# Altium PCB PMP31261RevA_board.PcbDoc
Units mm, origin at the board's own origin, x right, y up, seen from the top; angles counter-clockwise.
Board outline 58.42 x 41.91 mm, 2 copper layers (Top Layer, Bottom Layer), stack 1.575 mm thick; 35 components, 18 nets, 85 pads, 16 vias.
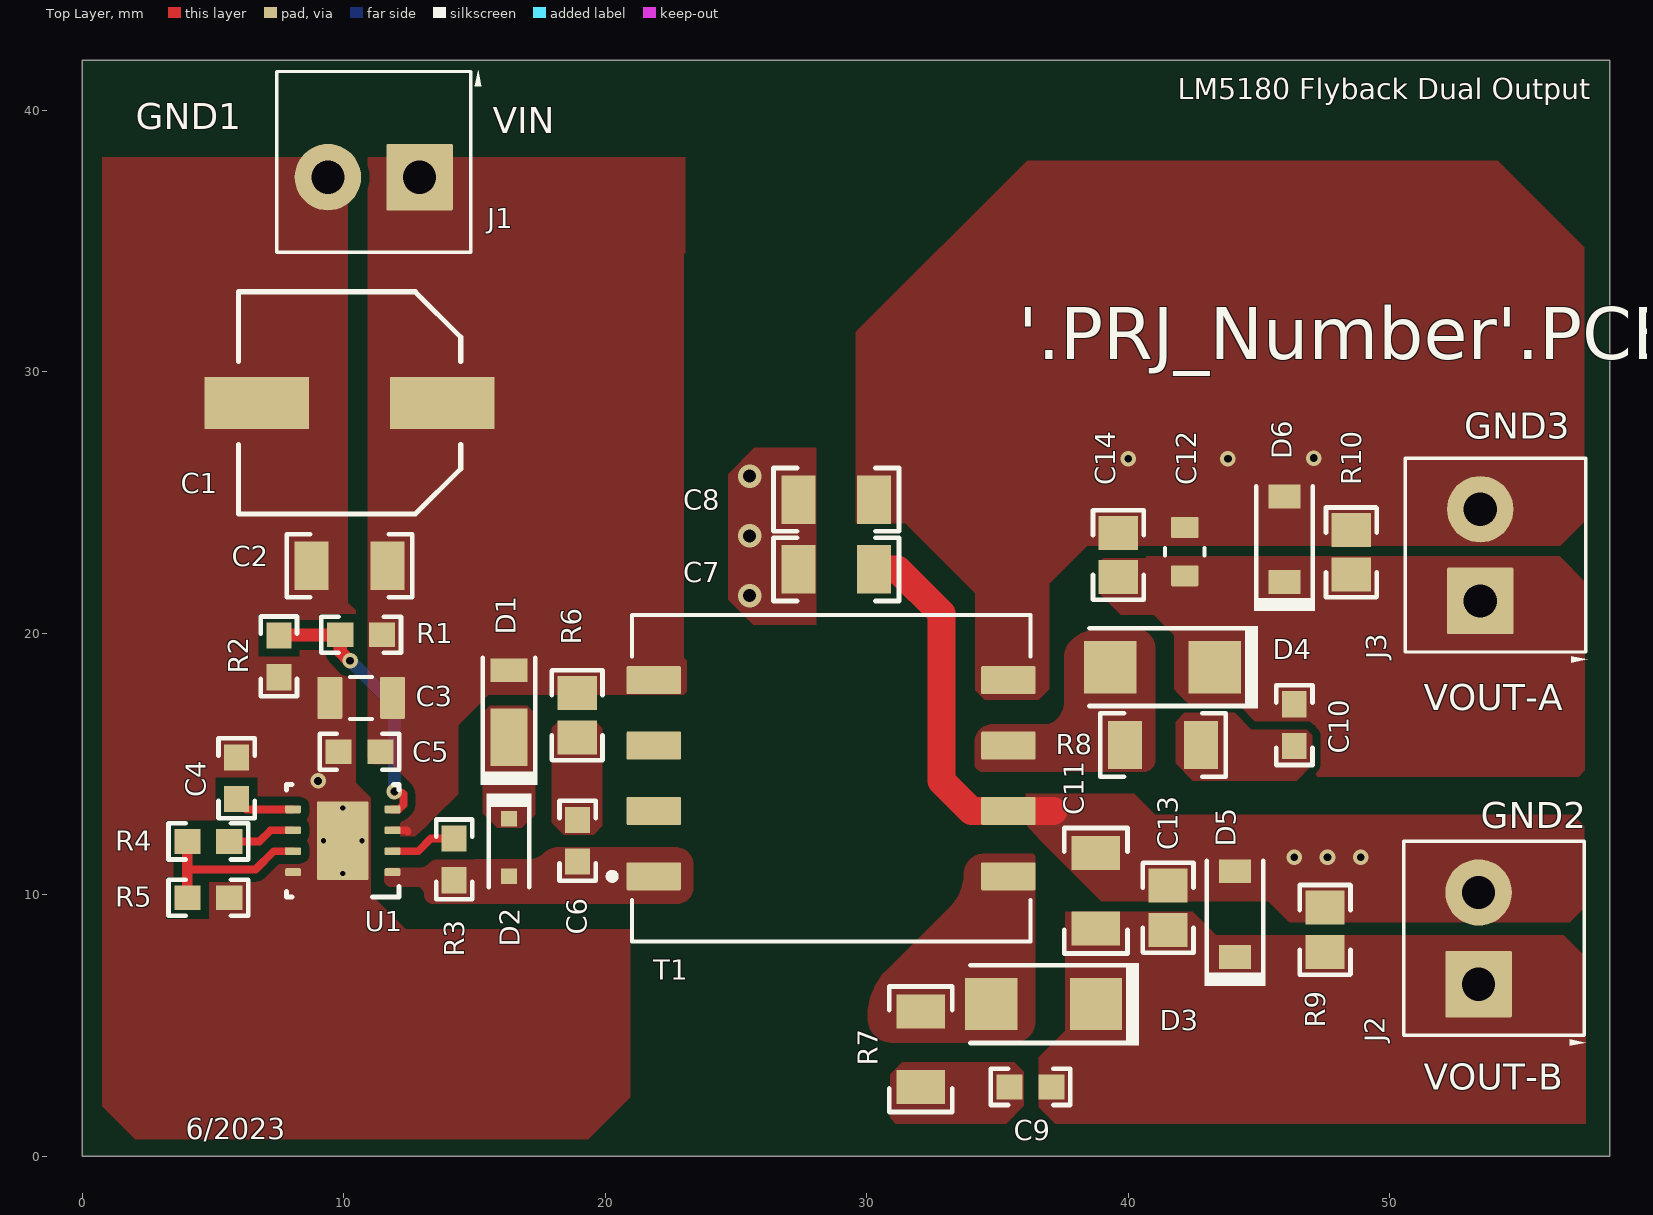
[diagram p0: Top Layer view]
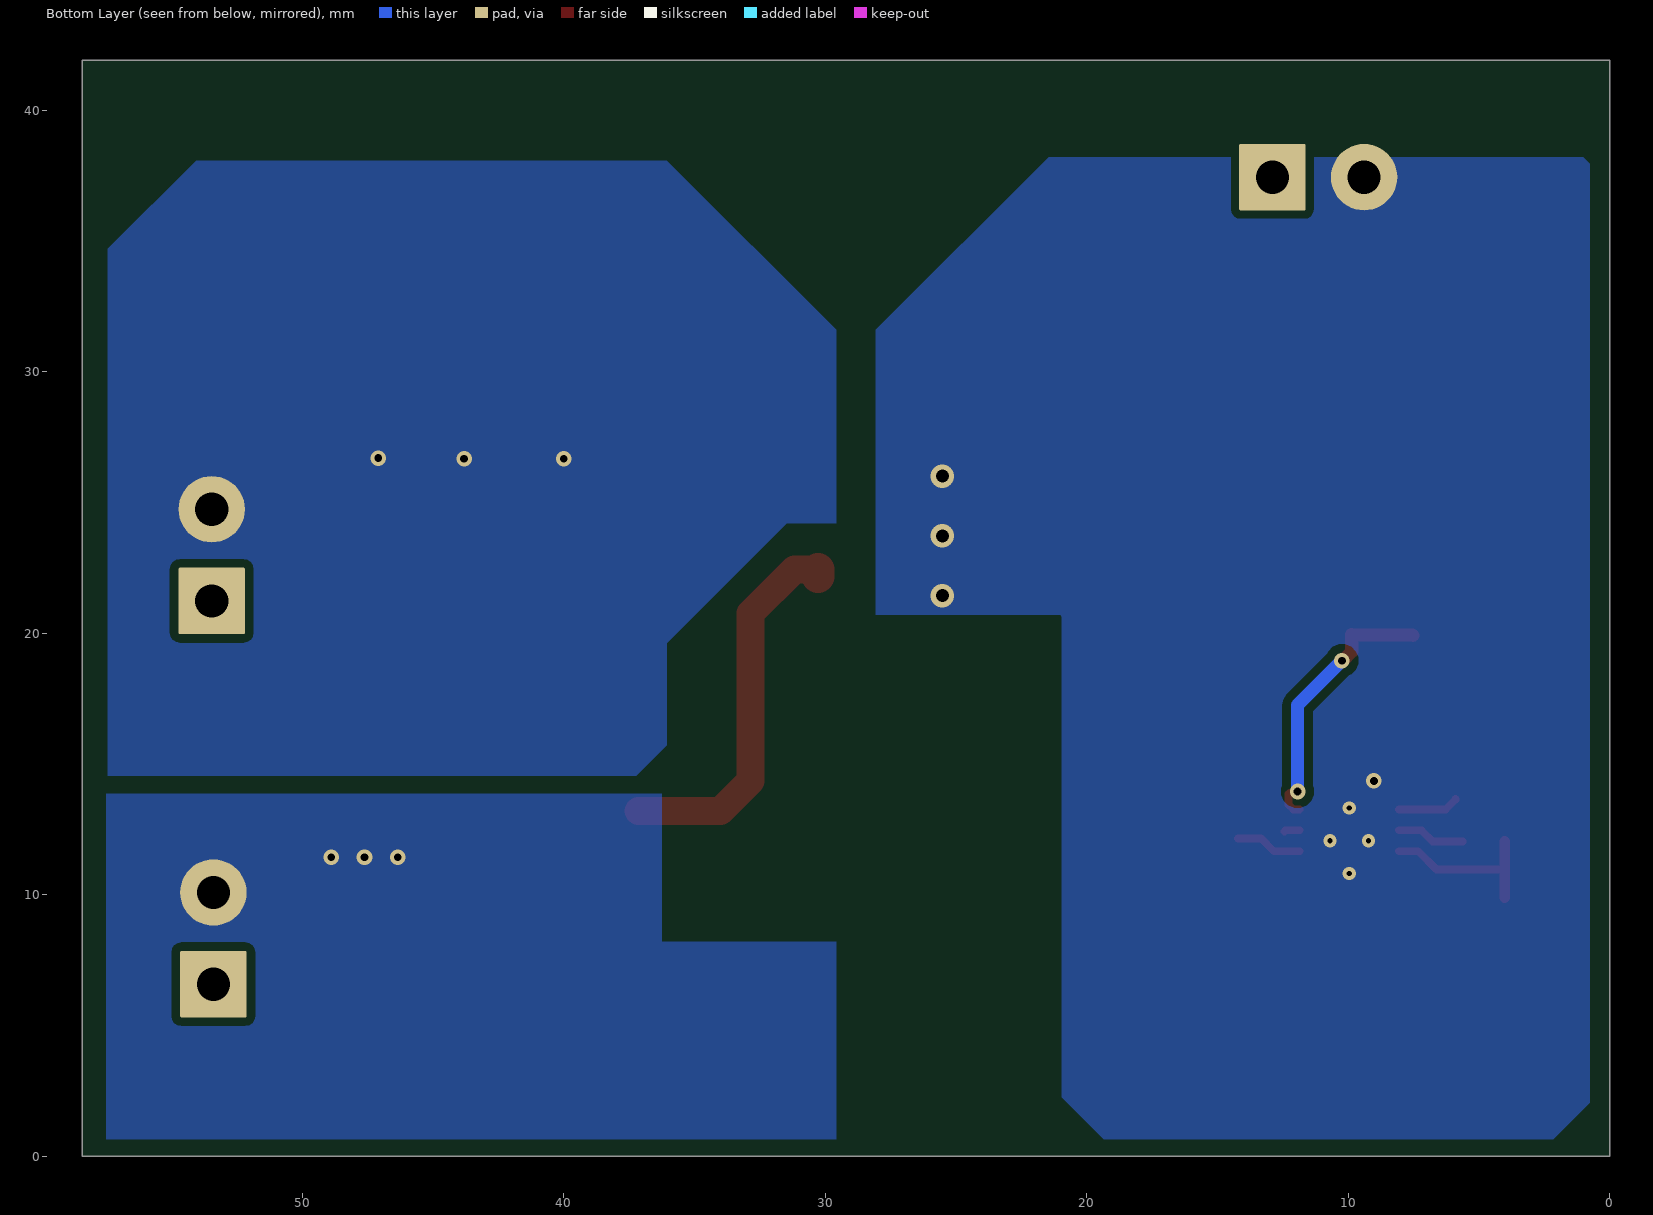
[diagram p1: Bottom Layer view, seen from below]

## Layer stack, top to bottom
Top Solder: solder mask 0.0102, Solder Resist, Dk 3.5
Top Layer: signal copper 0.0356
Dielectric1: core 1.5037, FR-4, Dk 4.8
Bottom Layer: signal copper 0.0356
Bottom Solder: solder mask 0.0102, Solder Resist, Dk 3.5

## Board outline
0,0 58.42,0 58.42,41.91 0,41.91

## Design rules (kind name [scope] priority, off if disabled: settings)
AcuteAngle [All] p1: minimum=4.50000000000000E+0001 checktracksonly=FALSE
AssemblyTestPointUsage [All] p1: valid=2
BoardOutlineClearance BoardOutlineClearance_MountingHoles [OnCopper and InComponentClass('Mounting Holes')] p1: gap=1 ignorepadtopadclearanceinfootprint=FALSE
BoardOutlineClearance BoardOutlineClearance_Poly [OnCopper and IsPoly] p2: gap=0.635 ignorepadtopadclearanceinfootprint=FALSE
BoardOutlineClearance [OnCopper and Not InComponentClass('Logo') and not InComponentClass('FiducialMark') and not InRegion(1000,500,4000,800) and not InPoly] p3: gap=1.905 ignorepadtopadclearanceinfootprint=FALSE
Clearance Clearance_Keepouts [((IsTrack Or IsArc) And Not InPoly) And IsFree and IsKeepOut vs ((IsTrack Or IsArc) And Not InPoly) And IsFree and IsKeepOut] p1: gap=0 ignorepadtopadclearanceinfootprint=FALSE
Clearance Clearance_Poly [InPolygon] p2: gap=0.32 ignorepadtopadclearanceinfootprint=TRUE
Clearance Clearance_FiducialMark [IsKeepOut and InComponentClass('FiducialMark') vs IsPad and InComponentClass('FiducialMark')] p3: gap=0 ignorepadtopadclearanceinfootprint=FALSE
Clearance [All] p4: gap=0.2 ignorepadtopadclearanceinfootprint=TRUE
ComponentClearance ComponentClearance_MountingHoles_FiducialMarks [InComponentClass('Mounting Holes') vs InComponentClass('FiducialMark')] p1: gap=1.27 collisioncheckmode=3 verticalgap=0.254 showdistances=FALSE
ComponentClearance ComponentClearance_Shunt [InComponentClass('Header') vs InComponentClass('Shunt')] p2: gap=0 collisioncheckmode=3 verticalgap=0 showdistances=FALSE
ComponentClearance ComponentClearance_Logo [InComponentClass('Logo')] p3: gap=1.27 collisioncheckmode=3 verticalgap=0.254 showdistances=FALSE
ComponentClearance ComponentClearance_ScrewToNut [(HasFootprint('NY PMS 440 0025 PH')) vs (HasFootprint('Keystone_1902C'))] p4: gap=0.127 collisioncheckmode=3 verticalgap=0.254 showdistances=FALSE
ComponentClearance ComponentClearance_MountingHoles [InComponentClass('Mounting Holes')] p5: gap=6.35 collisioncheckmode=3 verticalgap=2540 showdistances=FALSE
ComponentClearance ComponentClearance_SmallPassives [HasFootprint('0201*') or HasFootprint('0402*') or HasFootprint('0508') or HasFootprint('0603*') or HasFootprint('0612') or HasFootprint('0805*') or HasFootprint('0815*') or HasFootprint('0830*') or HasFootprint('1206*') or HasFootprint('1210*') or HasFootprint('1808*') or HasFootprint('1812*') or HasFootprint('1825*') or HasFootprint('2010*') or HasFootprint('2220*') or HasFootprint('2225*') or HasFootprint('2512*') or HasFootprint('2728*') or HasFootprint('3518*') vs HasFootprint('0201*') or HasFootprint('0402*') or HasFootprint('0508') or HasFootprint('0603*') or HasFootprint('0612') or HasFootprint('0805*') or HasFootprint('0815*') or HasFootprint('0830*') or HasFootprint('1206*') or HasFootprint('1210*') or HasFootprint('1808*') or HasFootprint('1812*') or HasFootprint('1825*') or HasFootprint('2010*') or HasFootprint('2220*') or HasFootprint('2225*') or HasFootprint('2512*') or HasFootprint('2728*') or HasFootprint('3518*')] p6: gap=0.38 collisioncheckmode=3 verticalgap=0.254 showdistances=FALSE
ComponentClearance ComponentClearance_THtoSMT [IsThruComponent vs IsSMTComponent] p7: gap=1.016 collisioncheckmode=3 verticalgap=0.762 showdistances=FALSE
ComponentClearance ComponentClearance_THtoTH [IsThruComponent vs IsThruComponent] p8: gap=0.762 collisioncheckmode=3 verticalgap=0.762 showdistances=FALSE
ComponentClearance [All] p9: gap=0.762 collisioncheckmode=3 verticalgap=0.254 showdistances=FALSE
DiffPairsRouting [All] p1: maxlimit=2.54 minlimit=0.254 mostfreqgap=0.254 toplayer_minwidth=0.381 toplayer_maxwidth=0.381 toplayer_prefwidth=0.381 bottomlayer_minwidth=0.381 bottomlayer_maxwidth=0.381 bottomlayer_prefwidth=0.381 maxuncoupledlength=25.4
FabricationTestPointUsage TestPointUsage [All] p1: valid=2 allowmultiple=FALSE
FabricationTestpoint Testpoint [All] p1: side=3 testpointundercomponent=TRUE minsize=1.016 maxsize=2.54 preferedsize=1.524 minholesize=0 maxholesize=1.016 preferedholesize=0.813 testpointgrid=0.025 allowsidetop=TRUE allowsidebottom=TRUE usegrid=TRUE gridtolerance=0
FanoutControl Fanout_LCC [IsLCC] p1: bgadir=Out bgaviamode=Centered fanoutstyle=Auto fanoutdirection=Alternating viagrid=0.025 // Fanout_LCC (Default Rule)
FanoutControl Fanout_BGA [IsBGA] p2: bgadir=Out bgaviamode=Centered fanoutstyle=Auto fanoutdirection=Alternating viagrid=0.025 // Fanout_BGA (Default Rule)
FanoutControl Fanout_Default [All] p4: bgadir=Out bgaviamode=Centered fanoutstyle=Auto fanoutdirection=Alternating viagrid=0.025 // Fanout_Default (Default Rule)
FanoutControl Fanout_Small [(CompPinCount < 5)] p5: bgadir=Out bgaviamode=Centered fanoutstyle=Auto fanoutdirection=OutThenIn viagrid=0.025 // Fanout_Small (Default Rule)
HoleSize [All] p1: absolutevalues=TRUE maxlimit=6.375 minlimit=0.3 maxpercent=80.000 minpercent=20.000
MinimumAnnularRing MinimumAnnularRing_ThermalPadVias [IsVia and InAnyComponent] p1: minimumring=0.15
MinimumAnnularRing [All] p2: minimumring=0.2
MinimumSolderMaskSliver MinimumSolderMaskSliver_Logo [InComponentClass('Logo') vs InComponentClass('Logo')] p1: minsoldermaskwidth=0.018
MinimumSolderMaskSliver [All] p2: minsoldermaskwidth=0.1
PlaneConnect [All] p1: planeconnectstyle=Relief reliefexpansion=0.254 reliefentries=4 reliefconductorwidth=0.254 reliefairgap=0.254
PolygonConnect [All] p1: connectstyle=Direct reliefconductorwidth=0.254 reliefentries=4 polygonreliefangle="90 Angle" airgapwidth=0.254
RoutingVias ThermalPadVias [IsVia and InAnyComponent] p1: holewidth=0.2 width=0.5 viastyle="Through Hole" minholewidth=0.2 minwidth=0.5 maxholewidth=0.33 maxwidth=0.6
RoutingVias [All] p2: holewidth=0.5 width=0.9 viastyle="Through Hole" minholewidth=0.3 minwidth=0.6 maxholewidth=1.016 maxwidth=1.651
SilkToBoardRegionClearance [Not ((IsComment or IsDesignator) And (Hide <> 'False')) and not InRegion(1000,500,4000,800)] p1:
SilkToSilkClearance SilkToSilkClearance_Pb-FreeLogo [(HasFootprint('Pb-Free_Overlay_Medium') OR HasFootprint('Pb-Free_Overlay_Small')) vs (HasFootprint('Pb-Free_Overlay_Medium') OR HasFootprint('Pb-Free_Overlay_Small'))] p1: silktosilkclearance=0
SilkToSilkClearance [All] p2: silktosilkclearance=0.1
SilkToSolderMaskClearance SilkToComponentPadClearance [(IsPad or IsFill or IsRegion) and InAnycomponent] p1: minsilkscreentomaskgap=0.127 clearancetoexposedcopper=TRUE
SilkToSolderMaskClearance "Silk to Solder Mask Opening" [All] p2: minsilkscreentomaskgap=0.1 clearancetoexposedcopper=FALSE
SolderMaskExpansion [All] p1: expansion=0.05 istentingtop=FALSE
UnRoutedNet [All] p1: checkbadconnections=TRUE
Width [All] p1: maxlimit=2.54 minlimit=0.152 preferedwidth=0.254 checkconnectedcopper=TRUE
14 further rules are at their usual default settings.

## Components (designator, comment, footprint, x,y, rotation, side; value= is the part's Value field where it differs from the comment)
C1 "EEEFP1H101AP" Panasonic_SMT_800x1020 10.224,28.8 r180 top value=100uF
C2 "Used in BOM report" 1206 10.224,22.577 r180 top
C3 "C2012X7R1H475K125AC" FP-C2012X7R1H475K125AC_0805-IPC_A 10.668,17.526 r0 top
C4 "C1608X7R1H473K080AA" 0603 5.906,14.449 r90 top value=0.047uF
C5 "C1608X7R1H104K080AA" 0603 10.605,15.465 r0 top value=0.1uF
C6 "Used in BOM report" 0603 18.942,12.059 r270 top
C7 "Used in BOM report" 1206 28.836,22.435 r180 top
C8 "Used in BOM report" 1206 28.836,25.105 r180 top
C9 "Used in BOM report" 0603 36.267,2.647 r180 top
C10 "Used in BOM report" 0603 46.355,16.481 r270 top
C11 "C3216X7R1E685K160AB" 1206 38.767,10.149 r90 top value=6.8uF
C12 "C2012X7R1H475K125AC" FP-C2012X7R1H475K125AC_0805-MFG 42.164,23.114 r270 top
C13 "Used in BOM report" 0805 41.529,9.496 r90 top
C14 "Used in BOM report" 0805 39.624,22.987 r90 top
D1 "DFLZ20-7" PowerDI123 16.321,17.297 r90 top value=20V
D2 "CMDD4448" SOD-323 16.321,11.805 r270 top value=75V
D3 "B180-13-F" SMA 36.767,5.813 r180 top value=80V
D4 "SS110-TP" SMA 41.314,18.699 r180 top value=100V
D5 "MMSZ5245B-7-F" SOD-123 44.082,9.256 r90 top value=15V
D6 "MMSZ5251B-7-F" SOD-123 45.983,23.585 r90 top value=22V
J1 "ED555/2DS" TERM_BLK_ED555-2DS 12.903,37.436 r180 top
J2 "ED555/2DS" TERM_BLK_ED555-2DS 53.404,6.575 r90 top
J3 "ED555/2DS" TERM_BLK_ED555-2DS 53.467,21.231 r90 top
R1 "CRCW0603147KFKEA" 0603 10.668,19.939 r0 top value=147k
R2 "CRCW060334K0FKEA" 0603 7.523,19.109 r90 top value=34.0k
R3 "CRCW0603124KFKEA" 0603 14.224,11.349 r270 top value=124k
R4 "CRCW0603243KFKEA" 0603 4.826,12.036 r180 top value=243k
R5 "CRCW060312K1FKEA" 0603 4.826,9.877 r180 top value=12.1k
R6 "Used in BOM report" 0805 18.929,16.856 r90 top
R7 "Used in BOM report" 1206 32.068,4.085 r270 top
R8 "Used in BOM report" 1206 41.339,15.719 r0 top
R9 "Used in BOM report" 0805 47.533,8.649 r270 top
R10 "Used in BOM report" 0805 48.533,23.085 r270 top
T1 "750320550r00" FP-750320550r00_SMT8_15MM24_12MM5-MFG 28.639,14.449 r180 top
U1 "LM5180NGUR" NGU0008C 9.965,12.059 r180 top

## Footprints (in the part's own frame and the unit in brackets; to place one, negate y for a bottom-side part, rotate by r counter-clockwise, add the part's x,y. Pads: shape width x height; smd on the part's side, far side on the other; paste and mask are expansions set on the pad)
0603 [mm] "0603 from SM-752 data"
  rect 1x0.95 smd: 1(-0.8,0) 2(0.8,0)
  silkscreen extent -1.52,-0.69 1.52,0.69, body extent -0.87,-0.47 0.87,0.47, height 1
0805 [mm] "0805 from SM-752 data"
  rect 1.3x1.5 smd: 1(-0.85,0) 2(0.85,0)
  silkscreen extent -1.72,-0.97 1.72,0.97, body extent -1.1,-0.72 1.1,0.72, height 1.45
1206 [mm] "1206 from SM-752 data"
  rect 1.3x1.85 smd: 1(-1.45,0) 2(1.45,0)
  silkscreen extent -2.4,-1.21 2.4,1.21, body extent -1.7,-0.9 1.7,0.9, height 1.35
FP-750320550r00_SMT8_15MM24_12MM5-MFG [mm]
  rrect9% 2.08x1.07 smd paste+0 mask+0: 1(6.78,3.75) 2(6.78,1.25) 3(6.78,-1.25) 4(6.78,-3.75) 5(-6.78,-3.75) 6(-6.78,-1.25) 7(-6.78,1.25) 8(-6.78,3.75)
  silkscreen extent -7.62,-6.25 8.49,6.25, body extent -7.92,-6.35 7.92,6.35, height 0.25
FP-C2012X7R1H475K125AC_0805-IPC_A [mm]
  rrect10% 0.956x1.606 smd paste+0 mask+0: 1(-1.2,0) 2(1.2,0)
  silkscreen extent -0.42,-0.8 0.42,0.8, body extent -2.18,-1.3 2.18,1.3, height 0.25
FP-C2012X7R1H475K125AC_0805-MFG [mm]
  rrect13% 0.8x1.05 smd paste+0 mask+0: 1(-0.925,0) 2(0.925,0)
  silkscreen extent -0.15,-0.75 0.15,0.75, body extent -1.43,-0.85 1.43,0.85, height 0.25
NGU0008C [mm] "SON, 8-Leads, Body 4x4mm, Pitch 0.8mm"
  rrect33% 0.6x0.3 smd: 1(-1.9,1.2) 2(-1.9,0.4) 3(-1.9,-0.4) 4(-1.9,-1.2) 5(1.9,-1.2) 6(1.9,-0.4) 7(1.9,0.4) 8(1.9,1.2)
  rrect8% 1.75x1.31 on Top Paste: 9(0,0.755) 9(0,-0.755)
  rrect5% 1.98x3 smd paste-1.5: 9(0,0)
  silkscreen extent -2.15,-2.15 2.15,2.15, body extent -2,-2 2,2, height 0.77
Panasonic_SMT_800x1020 [mm] "SMD, 2-Leads, Dia 8mm"
  rect 4x2 smd: 1(-3.55,0) 2(3.55,0)
  silkscreen extent -4.25,-4.25 4.25,4.25, body extent -4.25,-4.25 4.25,4.25, height 10.51
PowerDI123 [mm] "Diodes Inc recommended land pattern, document number DS30628 Rev. 6-2"
  rect 2.2x1.4 smd: 1(-1.275,0)
  rect 0.9x1.4 smd: 2(1.275,0)
  silkscreen extent -3.1,-1.09 1.76,1.09, body extent -2.38,-0.97 1.52,0.96, height 1
SMA [mm] "Molded Diode, 2-Leads, Body 4.3x2.6mm, IPC Medium Density, based on OnSemi component dimensions and land pattern"
  rect 2x2 smd: 1(-2,0) 2(2,0)
  silkscreen extent -3.66,-1.57 2.79,1.57, body extent -2.6,-1.3 2.6,1.3, height 2.42
SOD-123 [mm] "On Semi recommended land pattern"
  rect 0.915x1.22 smd: 1(-1.637,0) 2(1.637,0)
  silkscreen extent -2.74,-1.17 2.03,1.17, body extent -1.93,-0.9 1.93,0.9, height 1.35
SOD-323 [mm] "NXP recommended land pattern"
  rect 0.6x0.6 smd paste-0.05: 1(-1.1,0) 2(1.1,0)
  silkscreen extent -2.06,-0.86 1.53,0.86, body extent -1.3,-0.67 1.3,0.68, height 1.1
TERM_BLK_ED555-2DS [mil]
  rrect4% 100x100 hole 50: 1(0,0)
  round 100 hole 50: 2(138,0)
  silkscreen extent -93,-161 215,113, body extent -69,-150 207,106, height 323

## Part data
C1: library part CMP-0077295-1, "CAP, AL, 100 µF, 50 V, +/- 20%, 0.18 ohm, AEC-Q200 Grade 2, SMD", Cap_Case=8x10.2mm, Manufacturer=Panasonic, Supplier Part Number 1=P19726CT-ND, Tolerance_%=20%, Value1="0.18 ohm", Value2=50V, ValueDisplayed=100µF
C2 C6 C7 C8 C9 C10 C13 C14: library part Capacitor, "CAP, CERM, xxxF, xxV, [TempCo], xx%, [PackageReference]", Alternate Manufacturer=-
C3 C12: library part CMP-0088943-1, "4.7µF ±10% 50V Ceramic Capacitor X7R 0805 (2012 Metric)", Digikey Part Number=445-C2012X7R1H475K125ACCT-ND, Manufacturer=TDK, Mouser Part Number=810-C2012X7R475K125C, Operating Temperature Range="-55°C to +125°C", TempCo=15%, Temperature Characteristic=X7R, Tolerance_%=10%, ValueDisplayed=4.7uF
C4: library part CMP-0007049-4, "CAP, CERM, 0.047 uF, 50 V, +/- 10%, X7R, 0603", Cap_Case=0603, Manufacturer=TDK, Supplier Part Number 1=445-1313-1-ND, TempCo=X7R, Tolerance_%=10%, Value1="0.049007 ohm", Value2=50V, ValueDisplayed=0.047uF
C5: library part CMP-0007044-5, "CAP, CERM, 0.1 uF, 50 V, +/- 10%, X7R, 0603", Cap_Case=0603, Manufacturer=TDK, Supplier Part Number 1=445-1314-1-ND, TempCo=X7R, Tolerance_%=10%, Value1="0.0296 ohm", Value2=50V, ValueDisplayed=0.1uF
C11: library part CMP-0008693-2, "CAP, CERM, 6.8 uF, 25 V, +/- 10%, X7R, 1206", Cap_Case=1206, Manufacturer=TDK, Supplier Part Number 1=445-7703-1-ND, TempCo=X7R, Tolerance_%=10%, Value1=Unknown, Value2=25V, ValueDisplayed=6.8uF
D1: library part CMP-0005414-4, "Diode, Zener, 20 V, 1 W, PowerDI123", Manufacturer="Diodes Inc.", Power_W=1W
D2: library part CMP-0029019-2, "Diode, Ultrafast, 75 V, 0.25 A, SOD-323", Manufacturer="Central Semiconductor", Value1=0.25A, Value2=1.2V
D3: library part CMP-0028393-2, "Diode, Schottky, 80 V, 1 A, SMA", Manufacturer="Diodes Inc.", Value1=1A, Value2=0.79V
D4: library part CMP-0028597-2, "Diode, Schottky, 100 V, 1 A, SMA", Manufacturer="Micro Commercial Components", Value1=1A, Value2=0.85V
D5: library part CMP-0005753-4, "Diode, Zener, 15 V, 500 mW, SOD-123", Manufacturer="Diodes Inc.", Power_W=500mW, Value1=0.5W
D6: library part CMP-0005757-4, "Diode, Zener, 22 V, 500 mW, SOD-123", Manufacturer="Diodes Inc.", Power_W=500mW, Value1=0.5W
J1 J2 J3: library part CMP-0074913-1, "Terminal Block, 3.5mm Pitch, 2x1, TH", Color=Grey, Current_A=6A, Manufacturer="On-Shore Technology", Supplier Part Number 1=ED1514-ND, Voltage_V=150V
R1: library part CMP-0022052-4, "RES, 147 k, 1%, 0.1 W, AEC-Q200 Grade 0, 0603", Manufacturer=Vishay-Dale, Power_W=100mW, Supplier Part Number 1=541-147KHCT-ND, TempCo="100 ppm/C", Tolerance_%=1%, Value2=0.1W, Value_Code=147k
R2: library part CMP-0022346-4, "RES, 34.0 k, 1%, 0.1 W, AEC-Q200 Grade 0, 0603", Manufacturer=Vishay-Dale, Power_W=100mW, Supplier Part Number 1=541-34.0KHCT-ND, TempCo="100 ppm/C", Tolerance_%=1%, Value2=0.1W, Value_Code=34k0, ValueDisplayed=34.0k
R3: library part CMP-0022026-4, "RES, 124 k, 1%, 0.1 W, AEC-Q200 Grade 0, 0603", Manufacturer=Vishay-Dale, Power_W=100mW, Supplier Part Number 1=541-124KHCT-ND, TempCo="100 ppm/C", Tolerance_%=1%, Value2=0.1W, Value_Code=124k
R4: library part CMP-0022232-4, "RES, 243 k, 1%, 0.1 W, AEC-Q200 Grade 0, 0603", Manufacturer=Vishay-Dale, Power_W=100mW, Supplier Part Number 1=541-243KHCT-ND, TempCo="100 ppm/C", Tolerance_%=1%, Value2=0.1W, Value_Code=243k
R5: library part CMP-0022030-4, "RES, 12.1 k, 1%, 0.1 W, AEC-Q200 Grade 0, 0603", Manufacturer=Vishay-Dale, Power_W=100mW, Supplier Part Number 1=541-12.1KHCT-ND, TempCo="100 ppm/C", Tolerance_%=1%, Value2=0.1W, Value_Code=12k1, ValueDisplayed=12.1k
R6 R7 R8 R9 R10: library part Resistor, "RES, xxx ohm, x%, xW, [PackageReference]", Alternate Manufacturer=-
T1: library part CMP-0035051-1, "TRANSFORMER", Frequency_Fixed=100-350kHz, Manufacturer="Wurth Electronics", Operating Temperature Range="-40°C to +125°C", Voltage_Isolation_Vrms=1.5kV
U1: library part CMP-0084791-1, "70-VIN PSR Flyback DC/DC Converter With 100-V, 1.5-A Integrated Power MOSFET, NGU0008C (WSON-8)", Alternate Manufacturer="Texas Instruments", Alternate PartNumber=LM5180NGUT

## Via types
v1: diameter 0.6, hole 0.3, Top Layer to Bottom Layer, tented both sides, 6 vias
v2: diameter 0.5, hole 0.2, Top Layer to Bottom Layer, 4 vias
v3: diameter 0.6, hole 0.3, Top Layer to Bottom Layer, tented top, 3 vias
v4: diameter 0.9, hole 0.5, Top Layer to Bottom Layer, 3 vias

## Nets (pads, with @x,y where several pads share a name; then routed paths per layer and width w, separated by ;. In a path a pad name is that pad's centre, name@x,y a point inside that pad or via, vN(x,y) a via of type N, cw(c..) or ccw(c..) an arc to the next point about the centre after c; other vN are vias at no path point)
12V-OUT: C9.1 C11.1 C13.1 D3.1 D5.1 J2.1 R9.2
18V-OUT: C10.1 C12.2 C14.1 D4.1 D6.1 J3.1 R10.2
GND1: C1.2 C2.2 C3.1 C4.2 C5.1 C7.2 C8.2 J1.2 R2.1 R5.1 U1.8 U1.9@9.965,12.059
  other v2: 9.965,10.809 9.225,12.059 10.705,12.059 9.965,13.309
  other v3: 9.024,14.351
  other v4: 25.527,21.434 25.527,23.72 25.527,26.005
GND2: C7.1 C11.2 C13.2 D5.2 J2.2 R9.1 T1.7 | length 14.7
  Top Layer w1.07: C7.1 31.186,22.435 32.862,20.76 32.862,14.346 34.009,13.199 T1.7 37.139,13.199 37.149,13.189
  Top Layer w1.27: C7.1@30.286,22.16 C7.1
  other v1: 46.355,11.43 47.625,11.43 48.895,11.43
GND3: C8.1 C12.1 C14.2 D6.2 J3.2 R10.1 T1.5
  other v1: 40.005,26.67 43.815,26.67 47.1,26.692
NetC4_1: C4.1 U1.5 | length 2.3
  Top Layer w0.3: C4.1 5.906,13.624 6.271,13.259 U1.5
NetC6_1: C6.1 R6.1
NetC9_2: C9.2 R7.2
NetC10_2: C10.2 R8.2
NetD1_1: D1.1 D2.1
NetR1_1: R1.1 R2.2 U1.4 | length 10.5
  Top Layer w0.3: U1.4 12.109,13.259 12.284,13.435 12.284,13.841 12.242,13.884 11.995,13.884 v3(11.938,13.941)
  Top Layer w0.5: R2.2 7.538,19.924 9.853,19.924 R1.1 9.868,19.297 10.219,18.945 v3(10.246,18.945)
  Bottom Layer w0.5: v3(10.246,18.945) 11.938,17.254 v3(11.938,13.941)
NetR3_1: R3.1 U1.2 | length 2.6
  Top Layer w0.3: U1.2 12.846,11.659 13.336,12.149 R3.1
NetR4_1: R4.1 U1.6 | length 2.6
  Top Layer w0.3: R4.1 6.784,12.036 7.207,12.459 U1.6
NetR4_2: R4.2 R5.2 U1.7 | length 6.5
  Top Layer w0.3: 4.026,10.964 6.628,10.964 7.324,11.659 U1.7
  Top Layer w0.4: R5.2 4.026,10.964 R4.2
SW-12V: D3.2 R7.1 T1.8
SW-18V: D4.2 R8.1 T1.6
SW-P: C6.2 D2.2 R3.2 T1.1 U1.1
VIN: C1.1 C2.1 C3.2 C5.2 D1.2 J1.1 R1.2 R6.2 T1.4 U1.3 | length 0.6
  Top Layer w0.3: U1.3 12.404,12.459 12.446,12.417
pads on no net: T1.2 T1.3 U1.9@9.965,11.304 U1.9@9.965,12.814

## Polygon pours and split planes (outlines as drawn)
GND2 on Top Layer "TOP_LAYER_GND2_P011" (solid, remove dead copper, pour order 11): 40.234,13.863 36.085,13.863 36.085,12.7 36.658,12.063 38.971,9.749 45.365,9.749 46.165,8.949 56.893,8.949 57.443,9.499 57.443,12.613 57.003,13.053 41.044,13.053
GND3 on Top Layer "TOP_LAYER_GND3_P016" (solid, remove dead copper, pour order 16): 38.44,23.335 36.983,21.879 36.983,17.853 36.576,17.446 34.517,17.446 34.157,17.806 34.157,21.522 31.474,24.205 29.591,24.205 29.591,31.53 36.132,38.071 54.131,38.071 57.443,34.759 57.443,24.253 56.525,23.335
18V-OUT on Top Layer "TOP_LAYER_18V-OUT_P015" (solid, remove dead copper, pour order 15): 45.095,14.509 41.754,17.851 41.754,19.921 40.976,20.699 39.724,20.699 38.899,21.525 38.899,22.718 39.117,22.935 56.5,22.935 57.466,21.969 57.466,14.748 57.227,14.509
18V-OUT on Top Layer "TOP_LAYER_18V-OUT_P014" (solid, remove dead copper, pour order 14): 46.566,16.784 44.972,16.784 44.364,17.392 42.212,17.392 41.839,17.766 41.839,19.438 42.198,19.797 44.598,19.797 45.365,19.03 45.365,18.304 45.664,18.005 46.898,18.005 47.152,17.751 47.08,17.679 47.08,16.929 46.935,16.785
NetC10_2 on Top Layer "TOP_LAYER_NETC10_2_P013" (solid, remove dead copper, pour order 13): 46.441,14.351 47.048,14.958 47.048,16.093 46.83,16.31 44.71,16.31 44.071,16.949 42.144,16.949 41.814,16.619 41.814,15.016 42.479,14.351
SW-18V on Top Layer "TOP_LAYER_SW-18V_P012" (solid, remove dead copper, pour order 12): 40.594,14.707 ccw(c40.594,15.157) 41.044,15.157 41.044,19.375 ccw(c40.234,19.375) 40.234,20.185 39.022,20.185 ccw(c39.022,18.444) 37.791,19.675 ccw(c38.354,19.112) 37.557,19.112 37.557,17.392 cw(c36.599,17.392) 37.276,16.714 cw(c36.779,17.212) 36.779,16.509 34.808,16.509 ccw(c34.808,15.832) 34.131,15.832 34.131,15.001 ccw(c34.426,15.001) 34.426,14.707
12V-OUT on Top Layer "TOP_LAYER_12V-OUT_P010" (solid, remove dead copper, pour order 10): 36.576,1.876 37.211,1.241 40.028,1.241 57.506,1.241 57.506,7.596 56.652,8.449 43.374,8.449 42.479,9.344 37.592,9.344 37.592,4.798 36.576,3.781
NetC9_2 on Top Layer "TOP_LAYER_NETC9_2_P009" (solid, remove dead copper, pour order 9): 35.333,1.241 36.014,1.922 36.014,3.223 35.652,3.585 31.356,3.585 30.893,3.122 30.893,1.463 31.115,1.241
SW-12V on Top Layer "TOP_LAYER_SW-12V_P008" (solid, remove dead copper, pour order 8): 36.447,5.151 cw(c35.624,5.151) 35.624,4.328 30.994,4.328 cw(c30.994,5.285) 30.036,5.285 30.036,5.334 cw(c32.576,5.334) 30.78,7.13 33.212,9.562 ccw(c31.994,10.781) 33.717,10.781 cw(c34.503,10.781) 34.503,11.567 36.325,11.567 cw(c36.325,11.444) 36.447,11.444
GND1 on Top Layer "TOP_LAYER_GND1_P007" (solid, remove dead copper, pour order 7): 28.067,20.311 25.665,20.311 24.701,21.275 24.701,26.075 25.708,27.081 28.067,27.081
GND1 on Top Layer "TOP_LAYER_GND1_P005" (solid, remove dead copper, pour order 5): 11.039,10.009 12.374,8.674 20.955,8.674 20.955,2.258 19.303,0.607 2.06,0.607 0.762,1.905 0.762,38.198 10.16,38.198 10.16,21.163 10.455,20.868 10.455,14.278 11.039,13.695
NetC6_1 on Top Layer "TOP_LAYER_NETC6_1_P004" (solid, remove dead copper, pour order 4): 18.415,12.29 17.961,12.744 17.961,16.377 18.204,16.619 19.641,16.619 19.897,16.364 19.897,12.629 19.558,12.29
NetD1_1 on Top Layer "TOP_LAYER_NETD1_1_P003" (solid, remove dead copper, pour order 3): 15.876,12.549 16.815,12.549 17.319,13.053 17.319,16.914 17.019,17.214 15.58,17.214 15.317,16.951 15.317,13.108
SW-P on Top Layer "TOP_LAYER_SW-P_P002" (solid, remove dead copper, pour order 2): 12.863,11.02 ccw(c12.863,11.58) 13.259,11.184 cw(c13.658,10.786) 13.658,11.349 17.086,11.349 ccw(c17.086,12.152) 17.653,11.584 cw(c18.186,11.051) 18.186,11.805 22.71,11.805 cw(c22.71,11.147) 23.368,11.147 23.368,10.284 cw(c22.733,10.284) 22.733,9.649 13.399,9.649 cw(c13.399,9.968) 13.081,9.968 13.081,10.004 ccw(c12.776,10.004) 12.776,10.309 11.793,10.309 cw(c11.793,10.549) 11.553,10.549 11.553,10.889 cw(c11.684,10.889) 11.684,11.02
VIN on Top Layer "TOP_LAYER_VIN_P001" (solid, remove dead copper, pour order 1): 23.01,37.974 11.813,26.777 11.813,15.012 12.624,14.2 12.624,13.189 12.155,12.72 12.155,12.223 12.758,12.223 14.376,13.841 14.376,16.478 15.546,17.647 23.01,17.647 23.114,17.751 23.114,18.945 23.01,19.049
VIN on Top Layer "TOP_LAYER_VIN_P000" (solid, remove dead copper, pour order 0): 10.922,38.198 10.922,15.224 11.155,14.99 12.513,14.99 14.237,16.714 14.237,25.722 23.062,34.547 23.062,38.198
GND3 on Bottom Layer "BOTTOM_LAYER_GND3_P018" (solid, remove dead copper, pour order 18): 29.591,24.205 31.474,24.205 36.068,19.611 36.068,15.703 37.226,14.544 49.692,14.544 57.443,14.544 57.443,34.696 54.067,38.071 36.068,38.071 29.591,31.594
GND1 on Bottom Layer "BOTTOM_LAYER_GND1_P006" (solid, remove dead copper, pour order 6): 20.955,2.258 19.303,0.607 2.197,0.607 0.762,2.042 0.762,37.944 1.016,38.198 21.463,38.198 28.067,31.594 28.067,20.699 21.019,20.699 20.955,20.635
GND2 on Bottom Layer "BOTTOM_LAYER_GND2_P017" (solid, remove dead copper, pour order 17): 29.591,8.199 36.259,8.199 36.259,13.863 57.506,13.863 57.506,0.607 29.591,0.607

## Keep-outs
Keep-Out Layer:
  text ".Layer_Name" at 14.656,-21.806 h1.52

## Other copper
Top Layer:
  text ".Layer_Name" at 14.656,-21.806 h1.52
Bottom Layer:
  text ".Layer_Name" at 14.656,-21.806 h1.52

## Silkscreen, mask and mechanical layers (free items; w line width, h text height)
Top Overlay:
  text "LM5180 Flyback Dual Output" at 41.906,40.424 h0.8
  text "GND1" at 2.057,39.263 h1
  text "VIN" at 15.696,39.11 h1
  text "'.PRJ_Number'.PCB_Rev" at 35.793,30.48 h2
  text "GND3" at 52.857,27.428 h1
  text "VOUT-A" at 51.314,17.047 h1
  text "GND2" at 53.492,12.534 h1
  text "VOUT-B" at 51.314,2.537 h1
  text "6/2023" at 3.962,0.648 h0.8
  text ".Layer_Name" at 14.656,-21.806 h1.52
Bottom Overlay:
  text ".Layer_Name" at 14.656,-21.806 h1.52
Top Paste:
  text ".Layer_Name" at 14.656,-21.806 h1.52
Bottom Paste:
  text ".Layer_Name" at 14.656,-21.806 h1.52
Top Solder:
  text ".Layer_Name" at 14.656,-21.806 h1.52
  text ".Layer_Name" at 14.656,-21.806 h1.52
Bottom Solder:
  text "'.PRJ_Number'.PCB_Rev" at 52.705,34.29 h2
  text ".Layer_Name" at 14.656,-21.806 h1.52
Drill Guide:
  text ".Layer_Name" at 14.656,-21.806 h1.52
M1 Board Outline:
  the board outline again, w0.254
  text ".Layer_Name" at 14.656,-21.806 h1.52
M2 Board Dimensions:
  rectangle: 0,-6.985 3.175,-3.81
  rectangle: 3.175,-10.16 12.7,-6.985
  lines w0.178: 0,-6.985 25.4,-6.985 ; 3.175,-10.16 3.175,-3.81 ; 6.35,-10.16 6.35,-3.81 ; 12.7,-10.16 12.7,-3.81 ; 19.05,-10.16 19.05,-3.81 ; 0,-10.16 25.4,-10.16 25.4,-3.81 0,-3.81 0,-10.16
  text "'.Print_Date' .Print_Time" at 4.01,44.015 h2
  text ".Layer_Name" at 14.656,-21.806 h1.52
M3 3D STEP Top:
  text ".Layer_Name" at 14.656,-21.806 h1.52
M4 3D STEP Bottom:
  text ".Layer_Name" at 14.656,-21.806 h1.52
M5 Assembly Top:
  lines w0.254: -7.417,-23.626 160.223,-23.626 ; -7.417,-18.462 160.274,-18.462 ; -7.417,-13.297 -7.417,-28.791 94.31,-28.791 160.274,-28.791 160.274,-13.297 -7.404,-13.297 -7.404,-28.791 32.614,-28.791 ; 55.194,-28.791 55.194,-13.297 ; 87.376,-18.462 87.376,-13.297 ; 108.712,-18.462 108.712,-13.297 ; 124.511,-28.956 124.511,-23.804
  text "COMPONENTS MARKED 'DNP' SHOULD NOT BE POPULATED." at 29.299,-8.09 h1.52
  text "ASSEMBLY VARIANT:" at 29.286,-11.024 h1.52
  text ".VariantName" at 55.601,-11.024 h1.52
  text "PCB VIEWED FROM TOP SIDE" at -5.804,-16.654 h1.52
  text "BOARD #:" at 57.099,-16.654 h1.52
  text ".PRJ_Number" at 70.955,-16.654 h1.52
  text "REV:" at 92.405,-16.654 h1.52
  text ".PCB_Rev" at 99.809,-16.654 h1.52
  text "SVN REV:" at 113.69,-16.654 h1.52
  text ".VersionControl_RevNumber" at 126.543,-16.654 h1.52
  text "TID #:" at 57.099,-21.819 h1.52
  text ".TID" at 70.955,-21.819 h1.52
  text "PLOT NAME =" at -5.804,-27.034 h1.52
  text ".plot_File_Name" at 14.656,-27.034 h1.52
  text "GENERATED    :" at 57.15,-27.034 h1.52
  text ".Print_Date" at 79.235,-27.034 h1.52
  text ".Print_Time" at 97.752,-27.034 h1.52
  text "TEXAS INSTRUMENTS" at 129.87,-27.034 h1.52
M6 Assembly Bottom:
  lines w0.254: -7.429,-18.474 160.261,-18.474 ; -7.379,-23.639 160.261,-23.639 ; 28.334,-28.969 28.334,-23.817 ; 44.133,-18.474 44.133,-13.31 ; 65.468,-18.474 65.468,-13.31 ; 97.65,-28.804 97.65,-13.31 ; 120.231,-28.804 160.249,-28.804 160.249,-13.31 -7.429,-13.31 -7.429,-28.804 58.534,-28.804 160.261,-28.804 160.261,-13.31
  text "COMPONENTS MARKED 'DNP' SHOULD NOT BE POPULATED." at 154.991,-8.077 h1.52
  text ".VariantName" at 128.473,-11.024 h1.52
  text "ASSEMBLY VARIANT:" at 154.864,-11.024 h1.52
  text ".VersionControl_RevNumber" at 26.302,-16.667 h1.52
  text "SVN REV:" at 39.154,-16.667 h1.52
  text ".PCB_Rev" at 53.035,-16.667 h1.52
  text "REV:" at 60.439,-16.667 h1.52
  text ".PRJ_Number" at 81.89,-16.667 h1.52
  text "BOARD #:" at 95.745,-16.667 h1.52
  text "PCB VIEWED FROM BOTTOM SIDE" at 158.648,-16.667 h1.52
  text ".TID" at 81.89,-21.831 h1.52
  text "TID #:" at 95.745,-21.831 h1.52
  text "TEXAS INSTRUMENTS" at 22.974,-27.047 h1.52
  text ".Print_Time" at 55.093,-27.047 h1.52
  text ".Print_Date" at 73.609,-27.047 h1.52
  text "GENERATED    :" at 95.694,-27.047 h1.52
  text ".plot_File_Name" at 138.189,-27.047 h1.52
  text "PLOT NAME =" at 158.648,-27.047 h1.52
M9 Title Sheet:
  drawing of 57 lines, arcs and shapes, not listed
  text "1" at 18.792,204.127 h1.78
  text "2" at 82.182,204.127 h1.78
  text "3" at 145.411,204.127 h1.78
  text "4" at 209.08,204.127 h1.78
  text "5" at 272.555,204.127 h1.78
  text "6" at 336.182,204.127 h1.78
  text "A" at -10.579,175.095 h1.78
  text "A" at 365.341,175.095 h1.78
  text "B" at -10.579,114.643 h1.78
  text "B" at 365.341,114.643 h1.78
  text "C" at -10.579,54.318 h1.78
  text "C" at 365.341,54.318 h1.78
  text "PROJECT TITLE:" at 288.125,7.048 h1.14
  text ".PRJ_Title" at 289.395,3.662 h1.78
  text "DESIGNED FOR:" at 288.125,-0.597 h1.14
  text ".PRJ_Customer" at 289.395,-4.153 h1.78
  text "D" at -10.579,-5.88 h1.78
  text "D" at 365.341,-5.88 h1.78
  text "FILE NAME:" at 288.125,-8.217 h1.14
  text ".PCB_File_Name_No_Path" at 289.395,-11.265 h1.78
  text "Texas Instruments (TI) and/or its licensors do not warrant the accuracy or completeness of this specification" at 161.9,-15.376 h1.14
  text "ENGINEER:" at 288.125,-15.583 h1.14
  text "LAYOUT BY:" at 326.352,-15.583 h1.14
  text "or any information contained therein. TI and/or its licensors do not warrant that this design will meet" at 160.757,-18.237 h1.14
  text ".PRJ_Engineer" at 289.395,-19.52 h1.78
  text ".PCB_Layout" at 327.635,-19.52 h1.78
  text "the specifications, will be suitable for your application or fit for any particular purpose, or will operate in" at 160.757,-21.099 h1.14
  text ".Layer_Name" at 14.656,-21.806 h1.52
  text "ALTIUM DESIGNER VERSION:" at 326.352,-23.457 h1.14
  text "an implementation. TI and/or its licensors do not warrant that the design is production worthy. You should" at 160.757,-23.961 h1.14
  text "completely validate and test your design implementation to confirm the system functionality for your application." at 161.9,-26.822 h1.14
  text ".print_Scale" at 289.395,-26.843 h1.78
  text ".Application_BuildNumber" at 327.635,-26.843 h1.78
  text "1" at 18.792,-32.093 h1.78
  text "2" at 82.182,-32.093 h1.78
  text "3" at 145.411,-32.093 h1.78
  text "4" at 209.08,-32.093 h1.78
  text "5" at 272.555,-32.093 h1.78
  text "6" at 336.182,-32.093 h1.78
M10 Fab Notes:
  drawing of 189 lines, arcs and shapes, not listed
  text "DESIGN INFORMATION" at 314.503,161.447 h1.52
  text "MIN. TRACK WIDTH:" at 298.131,158.091 h1.52
  text "8" at 325.976,158.091 h1.52
  text "MIL" at 329.907,158.091 h1.52
  text "MIN. CLEARANCE:" at 298.131,154.938 h1.52
  text "0.2" at 324.452,154.938 h1.52
  text "mm" at 329.907,154.938 h1.52
  text "MIN. VIA PAD SIZE:" at 298.131,151.785 h1.52
  text "24" at 325.214,151.785 h1.52
  text "MIL" at 329.907,151.785 h1.52
  text "0.05mm (2MIL)" at 315.784,148.486 h1.52
  text "MINIMUM ANNULAR RING" at 289.769,148.277 h1.52
  text "EXTERNAL" at 333.768,148.277 h1.52
  text "PER" at 294.849,145.48 h1.52
  text "IPC-D-275 CLASS 2 LEVEL C" at 300.437,145.48 h1.52
  text "MIL, HOLES" at 338.238,142.928 h1.52
  text "+/-" at 328.27,142.709 h1.52
  text "+/-" at 349.961,142.709 h1.52
  text "REGISTRATION TOLERANCES:" at 289.769,142.682 h1.52
  text "METAL" at 320.243,142.682 h1.52
  text "5" at 334.879,142.683 h1.52
  text "3" at 356.037,142.683 h1.52
  text "MIL" at 358.99,142.682 h1.52
  text "HOLE SIZE TOLERANCE (UNLESS OTHERWISE SPECIFIED):" at 289.769,140.185 h1.52
  text "+/-" at 349.961,140.112 h1.52
  text "3" at 356.037,140.085 h1.52
  text "MIL" at 358.99,140.085 h1.52
  text "MATERIAL:" at 287.87,136.589 h1.52
  text "FR-4 High Tg" at 312.926,133.324 h1.52
  text "X" at 309.257,133.122 h1.52
  text "FR-408" at 298.563,133.007 h1.52
  text "OTHER" at 336.358,133.007 h1.52
  text "62 MIL (1.6mm) +/-10%" at 306.694,129.374 h1.52
  text "X" at 303.643,129.312 h1.52
  text "THICKNESS:" at 289.769,129.165 h1.52
  text "OTHER" at 339.33,129.165 h1.52
  text "TOLERANCE:" at 289.769,125.652 h1.52
  text "X" at 311.314,125.652 h1.52
  text "ANSI IPC-6012 TYPE 3 CLASS 2" at 315.836,125.652 h1.52
  text "OTHER +/-" at 315.835,121.989 h1.52
  text "BOW & TWIST:" at 289.769,118.302 h1.52
  text "X" at 311.314,118.302 h1.52
  text "ANSI IPC-6012 TYPE 3 CLASS 2" at 315.836,118.302 h1.52
  text "OTHER +/-" at 315.835,114.576 h1.52
  text "DRILLING:" at 287.87,111.258 h1.52
  text "NC_DRILL FILES" at 332.599,108.586 h1.52
  text "REFERENCE:" at 289.769,108.486 h1.52
  text "X" at 306.463,108.484 h1.52
  text "AS SHOWN" at 310.984,108.486 h1.52
  text "X" at 329.348,108.486 h1.52
  text "OTHER" at 340.168,104.873 h1.52
  text "PTH COPPER THICKNESS:" at 289.761,104.783 h1.52
  text "X" at 318.697,104.783 h1.52
  text "20-30 um" at 321.948,104.783 h1.52
  text "BOARD FINISH:" at 287.87,101.034 h1.52
  text "SILKSCREEN:" at 291.812,98.237 h1.52
  text "X" at 316.14,98.237 h1.52
  text "TOP" at 319.112,98.237 h1.52
  text "X" at 329.094,98.237 h1.52
  text "BOTTOM" at 332.091,98.237 h1.52
  text "SILKSCREEN COLOR:" at 291.812,94.295 h1.52
  text "X" at 316.115,94.295 h1.52
  text "WHITE" at 319.112,94.295 h1.52
  text "OTHER" at 332.091,94.295 h1.52
  text "X" at 319.442,90.652 h1.52
  text "GREEN" at 322.439,90.652 h1.52
  text "OTHER" at 338.136,90.652 h1.52
  text "SOLDER RESIST COLOR:" at 291.812,90.477 h1.52
  text "X" at 319.442,86.734 h1.52
  text "MATTE" at 322.439,86.734 h1.52
  text "SEMI-GLOSS" at 338.125,86.717 h1.52
  text "IMMERSION GOLD (ENIG)" at 314.819,82.345 h1.52
  text "ENEPIG" at 348.793,82.162 h1.52
  text "SURFACE FINISH:" at 287.87,82.136 h1.52
  text "X" at 310.298,82.136 h1.52
  text "IMM. TIN/SILVER OR EQUIV" at 296.24,78.649 h1.52
  text "OTHER" at 332.599,78.549 h1.52
  text "ARRAY/PANEL:" at 287.87,74.602 h1.52
  text "CUT AND TRIM PER M1 BOARD OUTLINE" at 314.819,74.393 h1.52
  text "N.C. ROUTE" at 314.819,70.94 h1.52
  text "X" at 332.295,70.94 h1.52
  text "V. SCORE" at 336.816,70.94 h1.52
  text "CERTIFICATION:" at 287.87,67.66 h1.52
  text "MATERIALS AND WORKMANSHIP FOR ALL PCBS" at 306.285,67.66 h1.52
  text "TO MEET OR EXCEED THE REQUIREMENTS OF:" at 306.285,65.271 h1.52
  text "X" at 297.078,62.003 h1.52
  text "ANSI IPC-A-600F CLASS ->" at 300.329,62.003 h1.52
  text "X" at 342.188,62.003 h1.52
  text "2" at 344.982,62.003 h1.52
  text "1" at 336.981,61.965 h1.52
  text "3" at 353.973,61.965 h1.52
  text "X" at 317.702,58.252 h1.52
  text "RoHS" at 320.953,58.252 h1.52
  text "OTHER" at 337.321,58.252 h1.52
  text "PER ORDER" at 347.407,58.252 h1.52
  text "ALL BOARDS MUST MEET OR EXCEED UL94-V0 REQUIREMENTS." at 288.569,54.345 h1.52
  text "PCB MUST BEAR THE UL94V-0 UL REGISTERED MATERIAL ID NUMBER" at 288.569,51.397 h1.52
  text "ADDITIONAL REQUIREMENTS:" at 287.87,47.094 h1.52
  text "MICROSECTION:" at 289.769,44.373 h1.52
  text "YES" at 312.775,44.373 h1.52
  text "REQUIRED" at 334.657,40.707 h1.52
  text "BARE BOARD ELEC. TEST:" at 289.769,40.634 h1.52
  text "NONE" at 322.935,40.634 h1.52
  text "X" at 331.66,40.634 h1.52
  text "PER ORDER" at 349.693,40.634 h1.52
  text "XX MIL VIAS REQUIRE NON-CONDUCTIVE FILL AND PLANARIZE" at 294.04,35.428 h1.5
  text "XX MIL VIAS REQUIRE CONDUCTIVE FILL AND PLANARIZE" at 294.243,32.787 h1.52
  text "OUTER XX MIL TRACES REQUIRE 50 OHM SINGLE-ENDED IMPEDANCE" at 294.218,28.637 h1.47
  text "LAYER 2 & 3 (INNER LAYERS) XX MIL WIDE, XX MIL SPACE / TRACES REQUIRE 100 OHM DIFFERENTIAL IMPEDANCE" at 294.015,22.65 h1.52
  text ".Layer_Name" at 14.656,-21.806 h1.52
M11 Gerber Information:
  lines w0.254: -7.417,-23.626 160.223,-23.626 ; -7.417,-18.462 160.274,-18.462 ; -7.417,-13.297 -7.417,-28.791 94.31,-28.791 160.274,-28.791 160.274,-13.297 -7.404,-13.297 -7.404,-28.791 32.614,-28.791 ; 55.194,-28.791 55.194,-13.297 ; 87.376,-18.462 87.376,-13.297 ; 108.712,-18.462 108.712,-13.297 ; 124.511,-28.956 124.511,-23.804
  text "ALL ARTWORK VIEWED FROM TOP SIDE" at -5.804,-16.654 h1.52
  text "BOARD #:" at 57.099,-16.654 h1.52
  text ".PRJ_Number" at 70.955,-16.654 h1.52
  text "REV:" at 92.405,-16.654 h1.52
  text ".PCB_Rev" at 99.809,-16.654 h1.52
  text "SVN REV:" at 113.69,-16.654 h1.52
  text ".VersionControl_RevNumber" at 126.543,-16.654 h1.52
  text "LAYER NAME =" at -5.804,-21.806 h1.52
  text "TID #:" at 57.099,-21.819 h1.52
  text ".TID" at 70.955,-21.819 h1.52
  text "PLOT NAME =" at -5.804,-27.034 h1.52
  text ".plot_File_Name" at 14.656,-27.034 h1.52
  text "GENERATED    :" at 57.15,-27.034 h1.52
  text ".Print_Date" at 79.235,-27.034 h1.52
  text ".Print_Time" at 97.752,-27.034 h1.52
  text "TEXAS INSTRUMENTS" at 129.87,-27.034 h1.52
M12 Stackup:
  drawing of 191 lines, arcs and shapes, not listed
  text "Layer" at 249.119,194.31 h1.52
  text "Name" at 259.531,194.31 h1.52
  text "Material" at 283.147,194.31 h1.52
  text "Thickness" at 304.985,194.31 h1.52
  text "Constant" at 321.49,194.31 h1.52
  text "Board Layer Stack" at 335.965,194.31 h1.52
  text "Top Overlay" at 259.531,191.262 h1.52
  text "Top Solder" at 259.531,188.214 h1.52
  text "Solder Resist" at 283.147,188.214 h1.52
  text "0.40mil" at 304.985,188.214 h1.52
  text "3.5" at 321.49,188.214 h1.52
  text "1" at 249.119,185.166 h1.52
  text "Top Layer" at 259.531,185.166 h1.52
  text "1.40mil" at 304.985,185.166 h1.52
  text "Dielectric1" at 259.531,182.118 h1.52
  text "FR-4" at 283.147,182.118 h1.52
  text "59.20mil" at 304.985,182.118 h1.52
  text "4.8" at 321.49,182.118 h1.52
  text "2" at 249.119,179.07 h1.52
  text "Bottom Layer" at 259.531,179.07 h1.52
  text "1.40mil" at 304.985,179.07 h1.52
  text "Bottom Solder" at 259.531,176.022 h1.52
  text "Solder Resist" at 283.147,176.022 h1.52
  text "0.40mil" at 304.985,176.022 h1.52
  text "3.5" at 321.49,176.022 h1.52
  text "Bottom Overlay" at 259.531,172.974 h1.52
  text ".Layer_Name" at 14.656,-21.806 h1.52
M13 Component Bodies Top:
  text ".Layer_Name" at 14.656,-21.806 h1.52
M14 Component Bodies Bottom:
  text ".Layer_Name" at 14.656,-21.806 h1.52
M15 Courtyards Top:
  text ".Layer_Name" at 14.656,-21.806 h1.52
M16 Courtyards Bottom:
  text ".Layer_Name" at 14.656,-21.806 h1.52
Drill Drawing:
  circle w0.254: c136.241,84.176 r0.703
  lines w0.254: 135.538,73.986 136.944,73.986 136.944,75.392 135.538,75.392 135.538,73.986 ; 135.538,77.5 135.89,77.5 136.241,77.149 136.593,77.5 136.944,77.5 136.593,77.851 136.944,78.203 136.593,78.203 136.241,78.554 135.89,78.203 135.538,78.203 135.89,77.851 135.538,77.5 ; 135.538,81.716 136.944,81.716 136.241,80.311 135.538,81.716
  lines w0.305: 134.264,73.038 216.362,73.038 ; 134.264,85.687 216.362,85.687 ; 142.85,69.875 142.85,88.849 ; 151.287,69.875 151.287,88.849 ; 167.453,69.875 167.453,88.849 ; 174.037,69.875 174.037,88.849 ; 183.568,69.875 183.568,88.849 ; 201.972,69.875 201.972,88.849 ; 134.264,69.875 216.362,69.875 216.362,88.849 134.264,88.849 134.264,69.875
  text "Symbol" at 136.162,86.636 h1.83
  text "Quantity" at 143.799,86.636 h1.83
  text "Finished Hole Size" at 152.235,86.636 h1.83
  text "Plated" at 168.402,86.636 h1.83
  text "Hole Type" at 174.986,86.636 h1.83
  text "Drill Layer Pair" at 184.517,86.636 h1.83
  text "Hole Tolerance" at 202.92,86.636 h1.83
  text "4" at 143.799,83.473 h1.52
  text "7.87mil (0.200mm)" at 152.235,83.473 h1.52
  text "PTH" at 168.402,83.473 h1.52
  text "Round" at 174.986,83.473 h1.52
  text "Top Layer - Bottom Layer" at 184.517,83.473 h1.52
  text "9" at 143.799,80.311 h1.52
  text "11.81mil (0.300mm)" at 152.235,80.311 h1.52
  text "PTH" at 168.402,80.311 h1.52
  text "Round" at 174.986,80.311 h1.52
  text "Top Layer - Bottom Layer" at 184.517,80.311 h1.52
  text "3" at 143.799,77.149 h1.52
  text "19.69mil (0.500mm)" at 152.235,77.149 h1.52
  text "PTH" at 168.402,77.149 h1.52
  text "Round" at 174.986,77.149 h1.52
  text "Top Layer - Bottom Layer" at 184.517,77.149 h1.52
  text "6" at 143.799,73.986 h1.52
  text "50.00mil (1.270mm)" at 152.235,73.986 h1.52
  text "PTH" at 168.402,73.986 h1.52
  text "Round" at 174.986,73.986 h1.52
  text "Top Layer - Bottom Layer" at 184.517,73.986 h1.52
  text "22 Total" at 143.799,70.824 h1.52
  text ".Layer_Name" at 14.656,-21.806 h1.52
M17 Embedded Cavity:
  text ".Layer_Name" at 14.656,-21.806 h1.52
M18 Embedded Assembly:
  text ".Layer_Name" at 14.656,-21.806 h1.52
M19 Embedded Keepout:
  text ".Layer_Name" at 14.656,-21.806 h1.52

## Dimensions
0,-10.16 to 25.4,-10.16 on M2 Board Dimensions
0,0 to 0,41.91 on M2 Board Dimensions
0,0 to 58.42,0 on M2 Board Dimensions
